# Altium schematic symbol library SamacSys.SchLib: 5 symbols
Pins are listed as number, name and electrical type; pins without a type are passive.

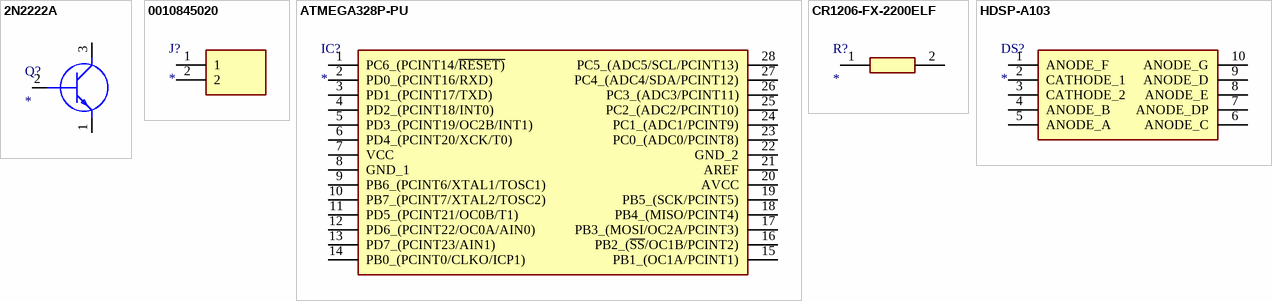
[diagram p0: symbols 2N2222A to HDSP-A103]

## 2N2222A
designator Q?
Transistor BJT NPN; Manufacturer_Name: Microsemi Corporation; Manufacturer_Part_Number: 2N2222A
footprint TO-18_4
pins: 1 E, 2 B, 3 C

## 0010845020
designator J?
Connector; Manufacturer_Name: Molex; Manufacturer_Part_Number: 0010845020
footprint 0010845020
pins: 1, 2

## ATMEGA328P-PU
designator IC?
Integrated Circuit; Manufacturer_Name: Microchip; Manufacturer_Part_Number: ATMEGA328P-PU; Allied_Number: 70332157
footprint DIP794W53P254L3467H457Q28N
pins: 1 PC6_(PCINT14/~{RESET)}, 2 PD0_(PCINT16/RXD), 3 PD1_(PCINT17/TXD), 4 PD2_(PCINT18/INT0), 5 PD3_(PCINT19/OC2B/INT1), 6 PD4_(PCINT20/XCK/T0), 7 VCC, 8 GND_1, 9 PB6_(PCINT6/XTAL1/TOSC1), 10 PB7_(PCINT7/XTAL2/TOSC2), 11 PD5_(PCINT21/OC0B/T1), 12 PD6_(PCINT22/OC0A/AIN0), 13 PD7_(PCINT23/AIN1), 14 PB0_(PCINT0/CLKO/ICP1), 15 PB1_(OC1A/PCINT1), 16 PB2_(~{SS}/OC1B/PCINT2), 17 PB3_(MOSI/OC2A/PCINT3), 18 PB4_(MISO/PCINT4), 19 PB5_(SCK/PCINT5), 20 AVCC, 21 AREF, 22 GND_2, 23 PC0_(ADC0/PCINT8), 24 PC1_(ADC1/PCINT9), 25 PC2_(ADC2/PCINT10), 26 PC3_(ADC3/PCINT11), 27 PC4_(ADC4/SDA/PCINT12), 28 PC5_(ADC5/SCL/PCINT13)

## CR1206-FX-2200ELF
designator R?
Resistor; Manufacturer_Name: Bourns; Manufacturer_Part_Number: CR1206-FX-2200ELF; Allied_Number: 70155093
footprint RESC3216X75N
pins: 1, 2

## HDSP-A103
designator DS?
Display; Manufacturer_Name: Avago Technologies; Manufacturer_Part_Number: HDSP-A103
footprint DIP508W51P254L1270H609Q10N
pins: 1 ANODE_F, 2 CATHODE_1, 3 CATHODE_2, 4 ANODE_B, 5 ANODE_A, 6 ANODE_C, 7 ANODE_DP, 8 ANODE_E, 9 ANODE_D, 10 ANODE_G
